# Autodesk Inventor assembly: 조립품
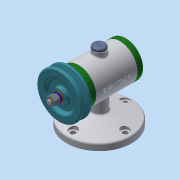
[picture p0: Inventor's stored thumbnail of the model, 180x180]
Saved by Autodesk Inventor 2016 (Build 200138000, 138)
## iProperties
Created: 2018-12
Part Number: 조립품
Material: 일반
Document SubType Name: Assembly
Designer: 605-12
Author: 605-12
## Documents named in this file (15)
- C:\Users\605-12\Desktop\481207V1007\조립품.iam
- C:\Users\605-12\Desktop\481207V1007\본체.ipt
- C:\Users\605-12\Desktop\481207V1007\베어링 15 x 32 x 9.ipt
- C:\Users\605-12\Desktop\481207V1007\축.ipt
- C:\Users\605-12\Desktop\481207V1007\뒤커버.ipt
- C:\Users\605-12\Desktop\481207V1007\앞커버.ipt
- C:\Users\605-12\Desktop\481207V1007\볼트 M4 x 12.ipt
- C:\Users\605-12\Desktop\481207V1007\키 3 x 3 x 12.ipt
- C:\Users\605-12\Desktop\481207V1007\오일 실 15 25 7.ipt
- C:\Users\605-12\Desktop\481207V1007\V벨트풀리.ipt
- C:\Users\605-12\Desktop\481207V1007\고무캡.ipt
- C:\Users\605-12\Desktop\481207V1007\와셔 8x17.ipt
- C:\Users\605-12\Desktop\481207V1007\스프링와셔 8.ipt
- C:\Users\605-12\Desktop\481207V1007\너트 M8.ipt
- 너트 M8.ipt
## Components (2 placed, 2 different names)
1. V벨트풀리:1
2. 고무캡:1
